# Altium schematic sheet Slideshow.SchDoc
size A; DocumentNumber: 1; SheetNumber: 1; SheetTotal: 1
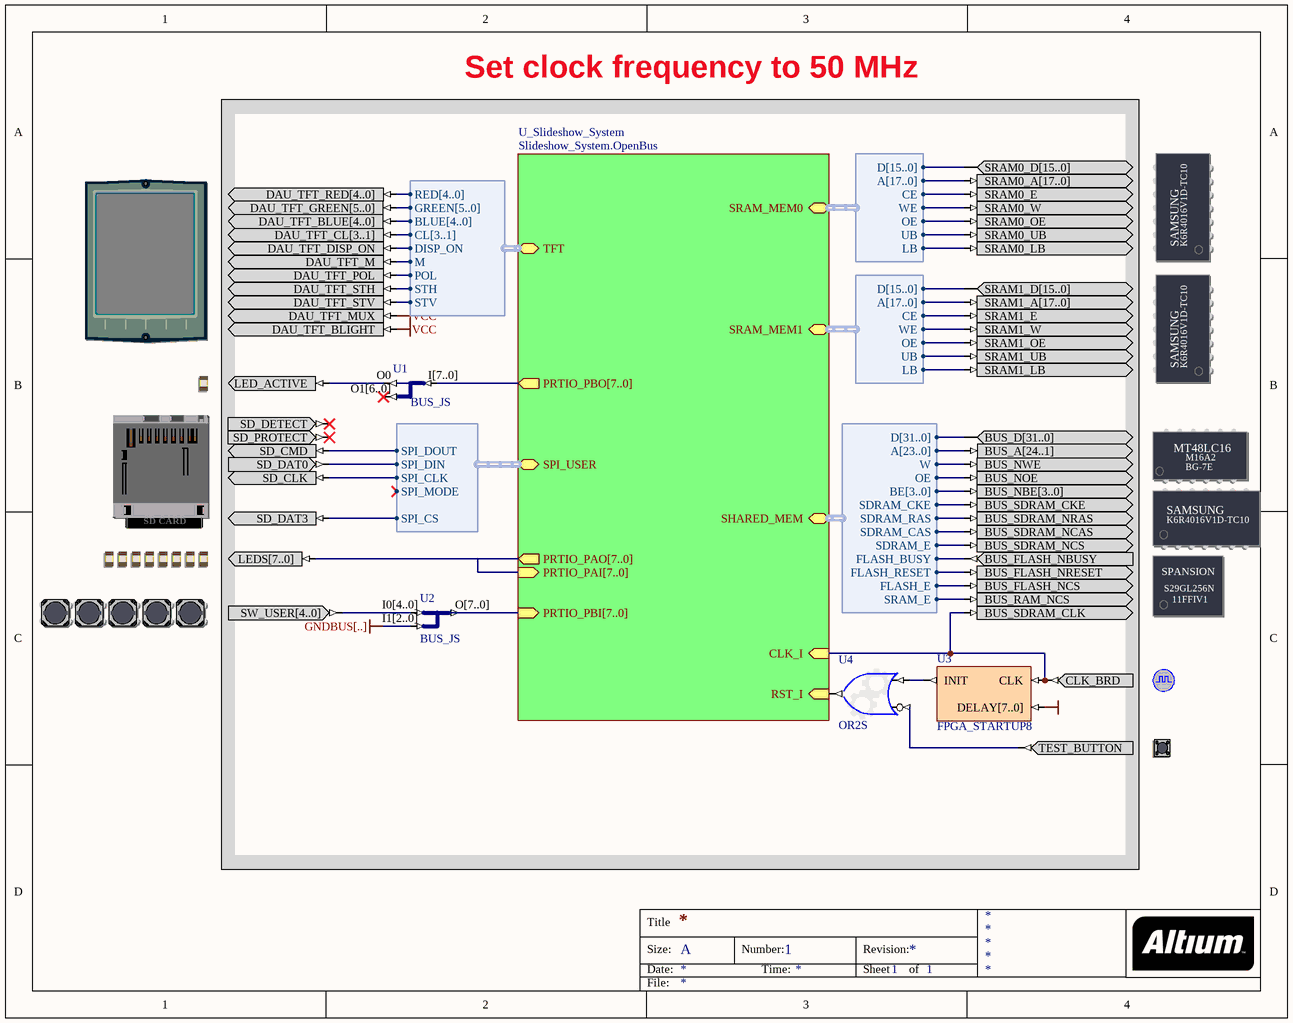
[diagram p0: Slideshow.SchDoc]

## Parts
(Parts that share a designator on the sheet are numbered #1, #2 ... from top to bottom, then left to right.)
?#1  SRAM_DAUGHTER0  (value not drawn)
?#2  TFT_LCD  (value not drawn)
?#3  SRAM_DAUGHTER1  (value not drawn)
?#4  LED_ACTIVE  (value not drawn)
?#5  SD_CARD  (value not drawn)
?#6  SHARED_MEM_DAUGHTER  (value not drawn)
?#7  LED  (value not drawn)
?#8  USER_BUTTONS  (value not drawn)
?#9  CLOCK_BOARD  (value not drawn)
?#10  TEST_BUTTON  (value not drawn)
U1  BUS_JS
U2  BUS_JS
U3  FPGA_STARTUP8
U4  OR2S

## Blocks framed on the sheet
Set clock frequency to 50 MHz: ?#1-?#10 U1-U4

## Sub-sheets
U_Slideshow_System = Slideshow_System.OpenBus: CLK_I (in), RST_I (in), PRTIO_PAO[7..0] (out), PRTIO_PAI[7..0] (in), PRTIO_PBO[7..0] (out), PRTIO_PBI[7..0] (in), SRAM_MEM0 (harness WB_MEM_CTRL_SRAM16_A18), SRAM_MEM1 (harness WB_MEM_CTRL_SRAM16_A18), SHARED_MEM (harness WB_SHARED_MEM_CTRL), TFT (harness VGA32_TFT), SPI_USER (harness SPI_W_NB)

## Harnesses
WB_MEM_CTRL_SRAM16_A18: D[15..0], A[17..0], CE, WE, OE, UB, LB
WB_SHARED_MEM_CTRL: D[31..0], A[23..0], W, OE, BE[3..0], SDRAM_CKE, SDRAM_RAS, SDRAM_CAS, SDRAM_E, FLASH_BUSY, FLASH_RESET, FLASH_E, SRAM_E
VGA32_TFT: RED[4..0], GREEN[5..0], BLUE[4..0], CL[3..1], DISP_ON, M, POL, STH, STV
SPI_W_NB: SPI_DOUT, SPI_DIN, SPI_CLK, SPI_MODE, SPI_CS

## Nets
VCC: ?#2.DAU_TFT_BLIGHT ?#2.DAU_TFT_MUX
VCCBUS[..]: U3.DELAY[7..0]
Net?#1_SRAM0_E: ?#1.SRAM0_E ; sheet U_Slideshow_System/SRAM_MEM0.CE
Net?#1_SRAM0_LB: ?#1.SRAM0_LB ; sheet U_Slideshow_System/SRAM_MEM0.LB
Net?#1_SRAM0_OE: ?#1.SRAM0_OE ; sheet U_Slideshow_System/SRAM_MEM0.OE
Net?#1_SRAM0_UB: ?#1.SRAM0_UB ; sheet U_Slideshow_System/SRAM_MEM0.UB
Net?#1_SRAM0_W: ?#1.SRAM0_W ; sheet U_Slideshow_System/SRAM_MEM0.WE
Net?#2_DAU_TFT_DISP_ON: ?#2.DAU_TFT_DISP_ON ; sheet U_Slideshow_System/TFT.DISP_ON
Net?#2_DAU_TFT_M: ?#2.DAU_TFT_M ; sheet U_Slideshow_System/TFT.M
Net?#2_DAU_TFT_POL: ?#2.DAU_TFT_POL ; sheet U_Slideshow_System/TFT.POL
Net?#2_DAU_TFT_STH: ?#2.DAU_TFT_STH ; sheet U_Slideshow_System/TFT.STH
Net?#2_DAU_TFT_STV: ?#2.DAU_TFT_STV ; sheet U_Slideshow_System/TFT.STV
Net?#3_SRAM1_E: ?#3.SRAM1_E ; sheet U_Slideshow_System/SRAM_MEM1.CE
Net?#3_SRAM1_LB: ?#3.SRAM1_LB ; sheet U_Slideshow_System/SRAM_MEM1.LB
Net?#3_SRAM1_OE: ?#3.SRAM1_OE ; sheet U_Slideshow_System/SRAM_MEM1.OE
Net?#3_SRAM1_UB: ?#3.SRAM1_UB ; sheet U_Slideshow_System/SRAM_MEM1.UB
Net?#3_SRAM1_W: ?#3.SRAM1_W ; sheet U_Slideshow_System/SRAM_MEM1.WE
Net?#4_LED_ACTIVE: ?#4.LED_ACTIVE U1.O0
Net?#5_SD_CLK: ?#5.SD_CLK ; sheet U_Slideshow_System/SPI_USER.SPI_CLK
Net?#5_SD_CMD: ?#5.SD_CMD ; sheet U_Slideshow_System/SPI_USER.SPI_DOUT
Net?#5_SD_DAT0: ?#5.SD_DAT0 ; sheet U_Slideshow_System/SPI_USER.SPI_DIN
Net?#5_SD_DAT3: ?#5.SD_DAT3 ; sheet U_Slideshow_System/SPI_USER.SPI_CS
Net?#6_BUS_FLASH_NBUSY: ?#6.BUS_FLASH_NBUSY ; sheet U_Slideshow_System/SHARED_MEM.FLASH_BUSY
Net?#6_BUS_FLASH_NCS: ?#6.BUS_FLASH_NCS ; sheet U_Slideshow_System/SHARED_MEM.FLASH_E
Net?#6_BUS_FLASH_NRESET: ?#6.BUS_FLASH_NRESET ; sheet U_Slideshow_System/SHARED_MEM.FLASH_RESET
Net?#6_BUS_NOE: ?#6.BUS_NOE ; sheet U_Slideshow_System/SHARED_MEM.OE
Net?#6_BUS_NWE: ?#6.BUS_NWE ; sheet U_Slideshow_System/SHARED_MEM.W
Net?#6_BUS_RAM_NCS: ?#6.BUS_RAM_NCS ; sheet U_Slideshow_System/SHARED_MEM.SRAM_E
Net?#6_BUS_SDRAM_CKE: ?#6.BUS_SDRAM_CKE ; sheet U_Slideshow_System/SHARED_MEM.SDRAM_CKE
Net?#6_BUS_SDRAM_CLK: ?#6.BUS_SDRAM_CLK ?#9.CLK_BRD U3.CLK ; sheet U_Slideshow_System/CLK_I
Net?#6_BUS_SDRAM_NCAS: ?#6.BUS_SDRAM_NCAS ; sheet U_Slideshow_System/SHARED_MEM.SDRAM_CAS
Net?#6_BUS_SDRAM_NCS: ?#6.BUS_SDRAM_NCS ; sheet U_Slideshow_System/SHARED_MEM.SDRAM_E
Net?#6_BUS_SDRAM_NRAS: ?#6.BUS_SDRAM_NRAS ; sheet U_Slideshow_System/SHARED_MEM.SDRAM_RAS
Net?#10_TEST_BUTTON: ?#10.TEST_BUTTON U4.I1
NetU3_INIT: U3.INIT U4.I0
NetU4_O: U4.O ; sheet U_Slideshow_System/RST_I

Not connected (* = marked no-connect by the designer): ?#1 SRAM0_A[17..0] SRAM0_D[15..0]; ?#2 DAU_TFT_BLUE[4..0] DAU_TFT_CL[3..1] DAU_TFT_GREEN[5..0] DAU_TFT_RED[4..0]; ?#3 SRAM1_A[17..0] SRAM1_D[15..0]; ?#5 SD_DETECT* SD_PROTECT*; ?#6 BUS_A[24..1] BUS_D[31..0] BUS_NBE[3..0]; ?#7 LEDS[7..0]; ?#8 SW_USER[4..0]; U1 I[7..0] O1[6..0]*; U2 I0[4..0] I1[2..0] O[7..0]

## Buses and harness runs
bus sheet U_Slideshow_System/PRTIO_PAI[7..0] = sheet U_Slideshow_System/PRTIO_PAO[7..0]

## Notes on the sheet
- Labels drawn without touching a wire or pin: GNDBUS[..]

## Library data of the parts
?#1 = SRAM_DAUGHTER0: Free Static RAM - Daughterboard; PortComponent: True
?#2 = TFT_LCD: TFT LCD Panel; PortComponent: True
?#3 = SRAM_DAUGHTER1: Free Static RAM - Daughterboard; PortComponent: True
?#4 = LED_ACTIVE: LED; PortComponent: True
?#5 = SD_CARD: Secure Digital Card Socket; PortComponent: True
?#6 = SHARED_MEM_DAUGHTER: Shared Memory - Daughterboard; PortComponent: True
?#7 = LED: Bank of eight Red LEDs; PortComponent: True
?#8 = USER_BUTTONS: Generic User Buttons; PortComponent: True
?#9 = CLOCK_BOARD: Global System Clock Supply; PortComponent: True
?#10 = TEST_BUTTON: Test / Reset Button; PortComponent: True
U1 = BUS_JS: Configurable Bus Joiner/Splitter; ConfiguratorName: GENERIC_BUS_JS; ConfigurationParameters: {}Version[1.0]{}SplitterJoinerType[Splitter]{}SignalCount[2]{}SignalWidth0[1]{}SignalWidth1[7]{}
U2 = BUS_JS: Configurable Bus Joiner/Splitter; ConfiguratorName: GENERIC_BUS_JS; ConfigurationParameters: {}Version[1.0]{}SplitterJoinerType[Joiner]{}SignalCount[2]{}SignalWidth0[5]{}SignalWidth1[3]{}
U3 = FPGA_STARTUP8: FPGA Startup With 8 Bit Delay
U4 = GATE: Configurable Generic Gate; ConfiguratorName: GENERIC_GATE; ConfigurationParameters: {}Version[1.0]{}GateKind[OR]{}BusInput[False]{}GateInputType[Bit]{}GateOutputOption[Normal]{}BusWidth[8]{}RegisterOutputs[False]{}NegativeClockEdge[False]{}InputCount[2]{}InputInvert0[False]{}InputInvert1[True]{}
